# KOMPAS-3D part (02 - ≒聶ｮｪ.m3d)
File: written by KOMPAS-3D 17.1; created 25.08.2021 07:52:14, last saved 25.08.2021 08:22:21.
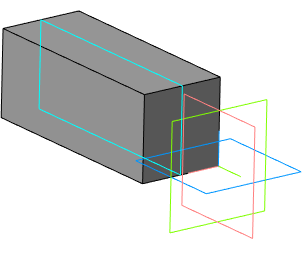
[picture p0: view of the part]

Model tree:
1. Эскиз:1
2. Элемент выдавливания:1
     Расстояние 2 = 100
3. Средняя плоскость:1
4. Отрезок:1
     Точка 1. Смещение (% от длины кривой) = 50; Точка 2. Смещение (% от длины кривой) = 50; Длина отрезка = 100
